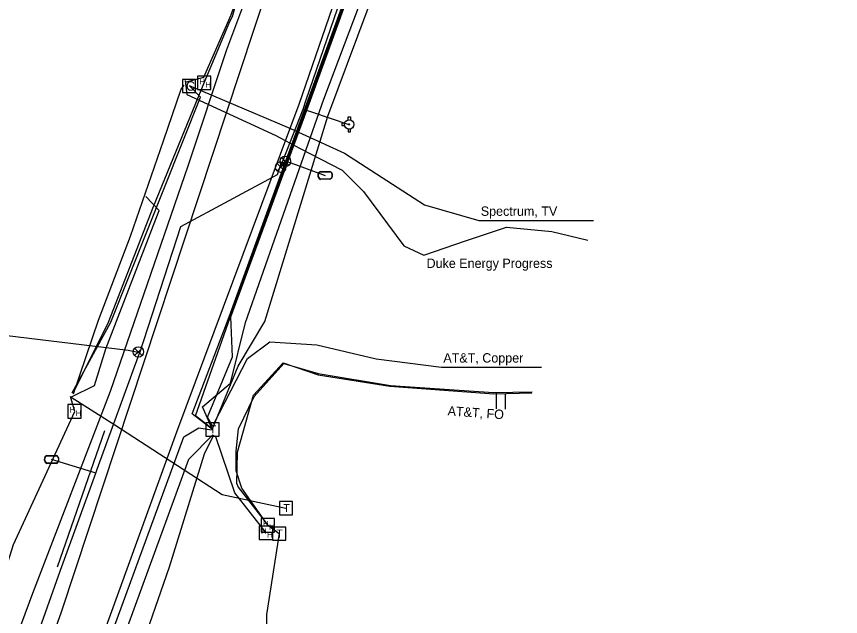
# Model space of a CAD drawing. Extents: x 2070721 to 2083340, y 729290 to 737883.
# Drawn here: x 2081212.7 to 2081564.9, y 733578.3 to 733834.7 of the extents above; entities that cross this region are included whole.
import ezdxf

# ---------------------------------------------------------------- set-up
doc = ezdxf.new("R2010")
doc.units = 0
for name, color, linetype in [('Exist Utilities Gas UG Line SUE LOS B', 7, 'Continuous'), ('Exist Utilities Other Unknown UG SUE LOS B', 7, 'Continuous'), ('Exist Utilities Power UG Cable SUE LOS B', 7, 'Continuous'), ('Exist Utilities Power UG Cable SUE LOS B Text', 7, 'Continuous'), ('Exist Utilities Telephone Hand Hole CELL', 7, 'Continuous'), ('Exist Utilities Telephone Pedestal CELL', 7, 'Continuous'), ('Exist Utilities Telephone UG Cable SUE LOS C', 7, 'Continuous'), ('Exist Utilities Telephone UG Cable SUE LOS C Text', 7, 'Continuous'), ('Exist Utilities Telephone UG FO SUE LOS B', 7, 'Continuous'), ('Exist Utilities Telephone UG FO SUE LOS B Leader', 7, 'Continuous'), ('Exist Utilities Telephone UG FO SUE LOS B Text', 7, 'Continuous'), ('Exist Utilities TV Hand Hole CELL', 7, 'Continuous'), ('Exist Utilities TV Pedestal CELL', 7, 'Continuous'), ('Exist Utilities TV UG Cable SUE LOS C', 7, 'Continuous'), ('Exist Utilities TV UG Cable SUE LOS C Text', 7, 'Continuous'), ('Exist Utilities TV UG FO Cable SUE LOS B', 7, 'Continuous'), ('Exist Utilities Water Fire Hydrant CELL', 7, 'Continuous'), ('Exist Utilities Water Meter CELL', 7, 'Continuous'), ('Exist Utilities Water UG Line SUE LOS B', 7, 'Continuous'), ('Exist Utilities Water Valve CELL', 7, 'Continuous')]:
    doc.layers.add(name, color=color, linetype=linetype)

msp = doc.modelspace()

# ---------------------------------------------------------------- linework, layer by layer
at = {"layer": 'Exist Utilities Gas UG Line SUE LOS B'}
msp.add_lwpolyline([(2081157.6, 733423.49), (2081157.75, 733423.93), (2081190.43, 733509.93), (2081219.7, 733588.19), (2081252.91, 733674.58), (2081286.02, 733770.88), (2081302.57, 733820.59), (2081312.47, 733846.89)], dxfattribs=at)
at = {"layer": 'Exist Utilities Other Unknown UG SUE LOS B'}
msp.add_line((2081230.17, 733599.51), (2081250.4, 733657.7), dxfattribs=at)
at = {"layer": 'Exist Utilities Power UG Cable SUE LOS B'}
for points in [[(2081284.81, 733807.36), (2081285.5, 733801.28), (2081323.58, 733783.74), (2081333.62, 733778.37)], [(2081333.62, 733778.37), (2081351.93, 733769), (2081360.99, 733759.87), (2081378.22, 733736.62), (2081386.74, 733732.7), (2081404.56, 733738.85), (2081422.08, 733744.58), (2081441.52, 733742.74), (2081456.96, 733739.11)], [(2081236.13, 733672.08), (2081246.06, 733676.96), (2081250.84, 733692.65), (2081273.67, 733751.71), (2081267.99, 733757.78)]]:
    msp.add_lwpolyline(points, dxfattribs=at)
at = {"layer": 'Exist Utilities Telephone Hand Hole CELL'}
for p, q in [((2081234.64, 733668.79), (2081234.64, 733663.06)), ((2081240.37, 733668.79), (2081234.64, 733668.79)), ((2081240.37, 733663.06), (2081240.37, 733668.79)), ((2081237.51, 733665.93), (2081237.51, 733665.93)), ((2081234.64, 733663.06), (2081240.37, 733663.06)), ((2081317.3, 733620.09), (2081317.3, 733614.36)), ((2081323.03, 733620.09), (2081317.3, 733620.09)), ((2081323.03, 733614.36), (2081323.03, 733620.09)), ((2081316.47, 733616.9), (2081316.47, 733611.18)), ((2081322.19, 733616.9), (2081316.47, 733616.9)), ((2081320.17, 733617.22), (2081320.17, 733617.22)), ((2081322.19, 733611.18), (2081322.19, 733616.9)), ((2081317.3, 733614.36), (2081323.03, 733614.36)), ((2081319.33, 733614.04), (2081319.33, 733614.04)), ((2081316.47, 733611.18), (2081322.19, 733611.18))]:
    msp.add_line(p, q, dxfattribs=at)
at = {"layer": 'Exist Utilities Telephone Pedestal CELL'}
for p, q in [((2081296.39, 733658.2), (2081296.39, 733658.2)), ((2081327.86, 733624.57), (2081327.86, 733624.57)), ((2081324.91, 733613.72), (2081324.91, 733613.72))]:
    msp.add_line(p, q, dxfattribs=at)
for points in [[(2081293.66, 733655.37), (2081299.26, 733655.37), (2081299.26, 733660.97), (2081293.66, 733660.97), (2081293.66, 733655.37)], [(2081325.14, 733621.74), (2081330.73, 733621.74), (2081330.73, 733627.34), (2081325.14, 733627.34), (2081325.14, 733621.74)], [(2081322.18, 733610.89), (2081327.78, 733610.89), (2081327.78, 733616.48), (2081322.18, 733616.48), (2081322.18, 733610.89)]]:
    msp.add_lwpolyline(points, dxfattribs=at)
at = {"layer": 'Exist Utilities Telephone UG Cable SUE LOS C'}
for points in [[(2080953.21, 732796.69), (2081054.09, 733077.62), (2081111.09, 733245.57), (2081176.08, 733423.78), (2081231.97, 733580.28), (2081320.16, 733847.08), (2081418.84, 734093.09), (2081467.34, 734224.03), (2081494.06, 734287.2), (2081526.74, 734352.01), (2081556, 734404.62), (2081808.13, 734757.73), (2081845.73, 734804.26), (2081874.67, 734821.58), (2081898.66, 734810.94), (2081917.15, 734795.51)], [(2081296.4, 733658.15), (2081287.8, 733664.8), (2081303.6, 733706.37), (2081324.3, 733763.14), (2081337.34, 733798.98), (2081373.91, 733899.45), (2081408.19, 733990.78), (2081432.67, 734050.1), (2081441.11, 734071.31), (2081457.65, 734065.9), (2081441.97, 734074.17), (2081465.76, 734134.1), (2081494.56, 734199.64), (2081510.1, 734235.63), (2081525.23, 734269.67), (2081532.48, 734287.03), (2081544.5, 734311.63), (2081547.42, 734317.11)], [(2081296.31, 733658.4), (2081289.16, 733664.06), (2081304.03, 733706.05), (2081324.8, 733762.93), (2081337.87, 733799.07), (2081374.5, 733899.39), (2081408.89, 733991.2), (2081433.1, 734049.99), (2081442.72, 734074.23), (2081467.51, 734133.17), (2081494.99, 734199.31), (2081510.48, 734235.4), (2081525.69, 734269.34), (2081544.76, 734311.53), (2081547.99, 734317.07)], [(2081296.39, 733658.2), (2081307.45, 733685.25), (2081318.77, 733704.29), (2081345.73, 733792.08), (2081384.21, 733895.19), (2081416.52, 733988.47), (2081438.43, 734048.05), (2081472.15, 734132.3), (2081497.77, 734194.3), (2081521.27, 734233.79), (2081552.24, 734307.58), (2081554.35, 734311.73)], [(2081296.32, 733658.45), (2081292.23, 733667.87), (2081304.13, 733678.02), (2081310.51, 733703.91), (2081344.1, 733799.36), (2081380.98, 733896.99), (2081413.3, 733989.25), (2081435.43, 734048.8), (2081469.68, 734133.31), (2081498.8, 734198.46), (2081514.35, 734234.28), (2081535.34, 734285.71)], [(2081296.61, 733659.46), (2081294.36, 733663.37), (2081305.04, 733689.21), (2081304.27, 733706.32), (2081325.1, 733762.82), (2081338.41, 733798.86), (2081374.68, 733899.14), (2081409.12, 733990.75), (2081435.11, 734049.06), (2081443.22, 734074.28), (2081470.18, 734132.86), (2081499.3, 734198.06), (2081514.4, 734234.31)], [(2081236.99, 733673.45), (2081247.78, 733704.87), (2081261.47, 733740.83), (2081275.48, 733781.49), (2081283.09, 733803.66), (2081284.37, 733805.31)], [(2081297.04, 733660.66), (2081311.38, 733688.44), (2081321.04, 733695.67), (2081341.02, 733694.28), (2081366.4, 733688.3), (2081394.37, 733684.77), (2081437.08, 733684.77)], [(2081236.04, 733672.01), (2081254.79, 733660.17), (2081300.55, 733630.39), (2081327.86, 733624.58)], [(2081252.65, 733568.73), (2081284.23, 733654.98), (2081290.61, 733658.83), (2081296.02, 733657.99)], [(2081257.51, 733566.68), (2081286.37, 733645.5), (2081296.64, 733655.96)], [(2081264.77, 733561.01), (2081264.9, 733561.27), (2081278.02, 733599.54), (2081293.06, 733647.81), (2081297.01, 733655.83)], [(2081324.91, 733613.72), (2081319.52, 733579.11), (2081319.52, 733562.34), (2081343.1, 733555.71), (2081356.84, 733548.33), (2081366.23, 733541.95), (2081371.13, 733535.72), (2081373.21, 733530.68)]]:
    msp.add_lwpolyline(points, dxfattribs=at)
at = {"layer": 'Exist Utilities Telephone UG FO SUE LOS B'}
for points in [[(2081248.81, 733567.64), (2081281.2, 733657.22), (2081333.49, 733797.21), (2081369.06, 733900.16), (2081403.11, 733993), (2081427.18, 734053.08), (2081460.75, 734136.42), (2081485.85, 734201.8), (2081501.51, 734239.63), (2081538.45, 734313.8), (2081542.88, 734322.62)], [(2081320.17, 733617.22), (2081309.01, 733633.17), (2081306.6, 733640.45), (2081306.6, 733648.93), (2081307.64, 733658.5), (2081314.26, 733672.29), (2081326.97, 733686.41), (2081341.67, 733682.07), (2081372.57, 733676.97), (2081416.57, 733673.92), (2081433.13, 733674.23)], [(2081306.87, 733635.01), (2081307.14, 733648.47), (2081313.93, 733672.81), (2081326.66, 733686.61), (2081341.59, 733681.48), (2081372.31, 733676.73), (2081416.7, 733673.36), (2081432.98, 733673.8)], [(2081060.57, 733214.24), (2081129.62, 733368.62), (2081142.99, 733409.6), (2081173.13, 733492.79), (2081185.02, 733525.68), (2081211.4, 733608.97), (2081237.57, 733665.91), (2081235.81, 733672.2)], [(2081319.38, 733613.95), (2081306.04, 733631.11), (2081297.82, 733655.43)], [(2081306.87, 733635.01), (2081307.41, 733633.56), (2081320.02, 733617.47), (2081324.92, 733613.79)]]:
    msp.add_lwpolyline(points, dxfattribs=at)
at = {"layer": 'Exist Utilities Telephone UG FO SUE LOS B Leader'}
for p, q in [((2081417.77, 733674.02), (2081417.77, 733667.05)), ((2081421.51, 733673.44), (2081421.51, 733666.83))]:
    msp.add_line(p, q, dxfattribs=at)
at = {"layer": 'Exist Utilities TV Hand Hole CELL'}
msp.add_line((2081292.89, 733806.33), (2081292.89, 733806.33), dxfattribs=at)
msp.add_lwpolyline([(2081290.02, 733803.45), (2081295.77, 733803.45), (2081295.77, 733809.2), (2081290.02, 733809.2), (2081290.02, 733803.45)], dxfattribs=at)
at = {"layer": 'Exist Utilities TV Pedestal CELL'}
msp.add_line((2081286.41, 733804.95), (2081286.41, 733804.95), dxfattribs=at)
msp.add_lwpolyline([(2081283.64, 733802.17), (2081289.19, 733802.17), (2081289.19, 733807.72), (2081283.64, 733807.72), (2081283.64, 733802.17)], dxfattribs=at)
at = {"layer": 'Exist Utilities TV UG Cable SUE LOS C'}
for points in [[(2081311.88, 733857.73), (2081311.69, 733856.75), (2081304.36, 733835.18), (2081292.68, 733808.59), (2081285.24, 733806.52)], [(2081236.49, 733673.89), (2081253.02, 733703.97), (2081291.28, 733800.23), (2081286.6, 733804.95)], [(2081286.47, 733805.11), (2081329.82, 733786.74), (2081352.93, 733776.2), (2081387.16, 733754.14), (2081410.29, 733747.47), (2081440.78, 733747.47), (2081459.29, 733747.47)]]:
    msp.add_lwpolyline(points, dxfattribs=at)
at = {"layer": 'Exist Utilities TV UG FO Cable SUE LOS B'}
for points in [[(2081305.07, 733834.62), (2081318.51, 733883.96), (2081344.94, 733950.24), (2081370.6, 734023.22), (2081385.26, 734060), (2081415.18, 734152.65), (2081441.55, 734219.41), (2081473.57, 734295.5), (2081490.54, 734320.82), (2081495.24, 734327.83)], [(2081236.98, 733673.69), (2081252.08, 733704.04), (2081271.3, 733753.5), (2081292.85, 733806.31), (2081303.91, 733832.48), (2081305.07, 733834.62)]]:
    msp.add_lwpolyline(points, dxfattribs=at)
at = {"layer": 'Exist Utilities Water Fire Hydrant CELL'}
msp.add_line((2081354.91, 733788.53), (2081354.91, 733788.53), dxfattribs=at)
for points in [[(2081354.4, 733790.44), (2081354.4, 733791.73), (2081355.43, 733791.73), (2081355.43, 733790.41)], [(2081353, 733789.04), (2081351.71, 733789.04), (2081351.71, 733788.01), (2081353, 733788.01)], [(2081354.4, 733786.61), (2081354.4, 733785.33), (2081355.43, 733785.33), (2081355.43, 733786.64)]]:
    msp.add_lwpolyline(points, dxfattribs=at)
for radius in [1.98, 0.243]:
    msp.add_circle((2081354.91, 733788.53), radius, dxfattribs=at)
at = {"layer": 'Exist Utilities Water Meter CELL'}
for p, q in [((2081344.64, 733766.77), (2081344.64, 733766.77)), ((2081227.69, 733645.4), (2081227.69, 733645.4))]:
    msp.add_line(p, q, dxfattribs=at)
for points in [[(2081342.61, 733768.47), (2081346.68, 733768.47)], [(2081342.61, 733768.33), (2081346.68, 733768.33)], [(2081346.68, 733765.2), (2081342.58, 733765.2)], [(2081346.68, 733765.07), (2081342.58, 733765.07)], [(2081225.66, 733647.1), (2081229.73, 733647.1)], [(2081229.73, 733643.83), (2081225.63, 733643.83)], [(2081229.73, 733643.7), (2081225.63, 733643.7)], [(2081225.66, 733646.96), (2081229.73, 733646.96)]]:
    msp.add_lwpolyline(points, dxfattribs=at)
for centre, radius, start, end in [((2081343.34, 733766.76), 1.86, 113.178, 245.9794), ((2081343.35, 733766.76), 1.73, 115.3009, 243.7824), ((2081345.94, 733766.77), 1.86, 293.6483, 66.3084), ((2081345.95, 733766.77), 1.73, 295.1272, 64.8728), ((2081226.39, 733645.39), 1.86, 113.178, 245.9794), ((2081228.99, 733645.4), 1.86, 293.6483, 66.3084), ((2081226.4, 733645.39), 1.73, 115.3009, 243.7824), ((2081229, 733645.4), 1.73, 295.1272, 64.8728)]:
    msp.add_arc(centre, radius, start, end, dxfattribs=at)
at = {"layer": 'Exist Utilities Water UG Line SUE LOS B'}
for points in [[(2081335.25, 733795.02), (2081336.53, 733799.05), (2081370.86, 733898.95), (2081404.78, 733992.12), (2081429.05, 734052.38), (2081463.19, 734135.61), (2081490.29, 734199.14)], [(2081326.64, 733773.23), (2081335.25, 733795.02)], [(2081335.25, 733795.02), (2081338.77, 733793.84), (2081354.81, 733788.48)], [(2081265.29, 733690.74), (2081265.37, 733690.97), (2081282.9, 733744.91), (2081324.22, 733767.16), (2081325.31, 733770.15), (2081325.7, 733771.11), (2081326.64, 733773.23)], [(2081326.64, 733773.23), (2081332.01, 733771.35), (2081344.65, 733766.73)], [(2081265.37, 733690.97), (2081260.45, 733691.91), (2081207.6, 733698.37)], [(2081246.63, 733639.55), (2081247.18, 733641.17), (2081265.29, 733690.74)], [(2081246.63, 733639.55), (2081245.38, 733639.93), (2081227.6, 733645.35)], [(2081199.8, 733508.96), (2081200.26, 733510.4), (2081231.43, 733598.04), (2081246.63, 733639.55)]]:
    msp.add_lwpolyline(points, dxfattribs=at)
at = {"layer": 'Exist Utilities Water Valve CELL'}
for points in [[(2081329.17, 733774.33), (2081326.02, 733771.18), (2081327.6, 733772.75), (2081329.17, 733771.18), (2081326.02, 733774.33)], [(2081327.2, 733771.86), (2081324.05, 733768.71), (2081325.62, 733770.28), (2081327.2, 733768.71), (2081324.05, 733771.86)], [(2081266.35, 733692.87), (2081263.2, 733689.72), (2081264.78, 733691.3), (2081266.35, 733689.72), (2081263.2, 733692.87)]]:
    msp.add_lwpolyline(points, dxfattribs=at)
for centre in [(2081327.6, 733772.75), (2081325.62, 733770.28), (2081264.78, 733691.3)]:
    msp.add_circle(centre, 2.23, dxfattribs=at)

# ---------------------------------------------------------------- texts
at = {"layer": 'Exist Utilities Power UG Cable SUE LOS B Text'}
msp.add_text('Duke Energy Progress', height=4, dxfattribs=at).set_placement((2081387.98, 733727.21))
at = {"layer": 'Exist Utilities Telephone Hand Hole CELL'}
for p in [(2081235.42, 733665.33), (2081237.99, 733663.87), (2081318.08, 733616.63), (2081317.25, 733613.45), (2081320.65, 733615.17), (2081319.82, 733611.98)]:
    msp.add_text('H', height=2.5, dxfattribs=at).set_placement(p)
at = {"layer": 'Exist Utilities Telephone Pedestal CELL'}
for p in [(2081295.26, 733656.49), (2081326.73, 733622.86), (2081323.78, 733612)]:
    msp.add_text('T', height=3.42, dxfattribs=at).set_placement(p)
at = {"layer": 'Exist Utilities Telephone UG Cable SUE LOS C Text'}
msp.add_text('AT&T, Copper', height=4, dxfattribs=at).set_placement((2081395.15, 733686.77))
at = {"layer": 'Exist Utilities Telephone UG FO SUE LOS B Text'}
msp.add_text('AT&T, FO', height=4, rotation=356.0382, dxfattribs=at).set_placement((2081396.88, 733664.2))
at = {"layer": 'Exist Utilities TV Hand Hole CELL'}
for p in [(2081290.8, 733805.68), (2081293.38, 733804.22)]:
    msp.add_text('H', height=2.5, dxfattribs=at).set_placement(p)
at = {"layer": 'Exist Utilities TV Pedestal CELL'}
msp.add_text('C', height=4, dxfattribs=at).set_placement((2081285.11, 733802.95))
at = {"layer": 'Exist Utilities TV UG Cable SUE LOS C Text'}
msp.add_text('Spectrum, TV ', height=4, dxfattribs=at).set_placement((2081411.15, 733749.47))

doc.saveas('drawing.dxf')
